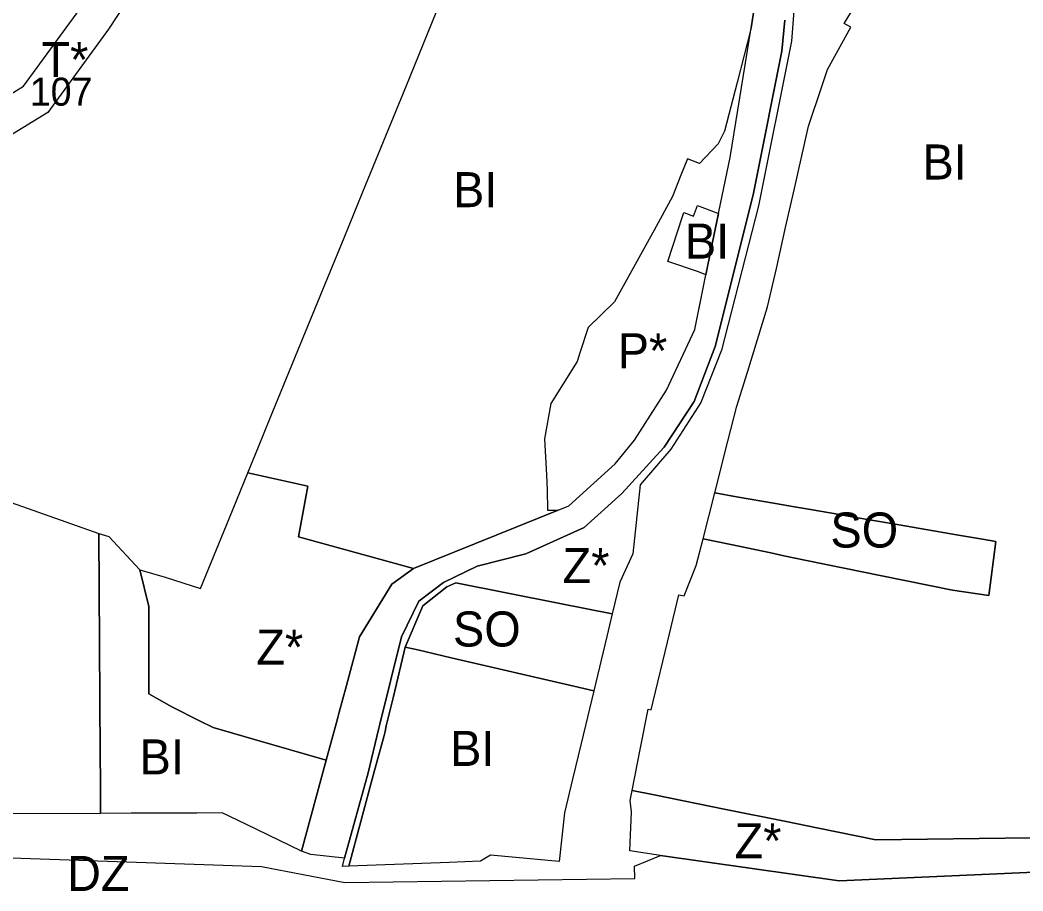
# Model space of a CAD drawing. Extents: x -521621 to -516769, y -1190068 to -1185078.
# Drawn here: x -519076.4 to -518790.4, y -1187170.7 to -1186922.3 of the extents above; entities that cross this region are included whole.
import ezdxf

# ---------------------------------------------------------------- set-up
doc = ezdxf.new("R2010")
doc.units = 0
for name, color, linetype in [('bydleni_s', 7, 'Continuous'), ('fpl_id', 7, 'Continuous'), ('s_zelen_s', 7, 'Continuous'), ('sm_vyuziti_s', 7, 'Continuous'), ('v_infrastr_n', 7, 'Continuous'), ('v_infrastr_s', 7, 'Continuous'), ('voda_s', 7, 'Continuous')]:
    doc.layers.add(name, color=color, linetype=linetype)

msp = doc.modelspace()

# ---------------------------------------------------------------- linework, layer by layer
at = {"layer": 'bydleni_s'}
for p, q in [((-518866.42, -1186914.8), (-518867.97, -1186924.47)), ((-518867.97, -1186924.47), (-518871.98, -1186940.13)), ((-518846.22, -1186936.39), (-518839.49, -1186924.32)), ((-518871.98, -1186940.13), (-518875.52, -1186953.98)), ((-518855.59, -1186970.29), (-518851.56, -1186952.52)), ((-518858.12, -1186981.47), (-518855.59, -1186970.29)), ((-518860.77, -1186993.13), (-518858.12, -1186981.47)), ((-518863.26, -1187004.11), (-518860.77, -1186993.13)), ((-518869.04, -1187022.77), (-518863.26, -1187004.11)), ((-519005.19, -1187036.06), (-518997.19, -1187016.52)), ((-518872.02, -1187032.4), (-518869.04, -1187022.77)), ((-518874.56, -1187042.38), (-518872.02, -1187032.4)), ((-519008.46, -1187044.05), (-519005.19, -1187036.06)), ((-518878.34, -1187057.18), (-518874.56, -1187042.38)), ((-518883.63, -1187077.91), (-518881.68, -1187070.28)), ((-518887.03, -1187086.48), (-518883.63, -1187077.91)), ((-518832.43, -1187156.14), (-518848.72, -1187152.83))]:
    msp.add_line(p, q, dxfattribs=at)
for points in [[(-518839.49, -1186924.32), (-518841.43, -1186923.31), (-518834.52, -1186911.88), (-518833.13, -1186912.44)], [(-518997.19, -1187016.52), (-518989.35, -1186997.36), (-518984.03, -1186984.36), (-518978.68, -1186971.28), (-518966.28, -1186940.98), (-518957.73, -1186920.08)], [(-518851.56, -1186952.52), (-518847.82, -1186941.21), (-518846.22, -1186936.39)], [(-518875.52, -1186953.98), (-518877.38, -1186957.58), (-518882.65, -1186963.16), (-518886.11, -1186961.88), (-518888.04, -1186966.5), (-518890.36, -1186972.63), (-518895.64, -1186982.24), (-518899.03, -1186988.43)], [(-518887.55, -1186978.34), (-518887.12, -1186977.18), (-518884.4, -1186978.2), (-518883.29, -1186975.22), (-518877.25, -1186977.48), (-518879.43, -1186987.93), (-518880.85, -1186994.95), (-518882.97, -1186994.14)], [(-518882.97, -1186994.14), (-518891.69, -1186991.15), (-518887.55, -1186978.34)], [(-518899.03, -1186988.43), (-518906.93, -1187002.63), (-518914.46, -1187009.96), (-518916.81, -1187017.23), (-518917.59, -1187019.65)], [(-518917.59, -1187019.65), (-518925.12, -1187031.63), (-518926.9, -1187041.73), (-518926.34, -1187052.15), (-518926.12, -1187056.17), (-518926.03, -1187062.09), (-518923.01, -1187062.07)], [(-518923.01, -1187062.07), (-518964.22, -1187078.77), (-518997.04, -1187069.74), (-518994.4, -1187055.27), (-519011.49, -1187051.47), (-519008.46, -1187044.05)], [(-518872.17, -1187058.25), (-518878.34, -1187057.18)], [(-518860.98, -1187060.18), (-518872.17, -1187058.25)], [(-518855.55, -1187061.12), (-518860.98, -1187060.18)], [(-518851.04, -1187061.9), (-518855.55, -1187061.12)], [(-518842.76, -1187063.33), (-518851.04, -1187061.9)], [(-518839.2, -1187063.95), (-518842.76, -1187063.33)], [(-518825.73, -1187066.28), (-518839.2, -1187063.95)], [(-518818.13, -1187067.59), (-518825.73, -1187066.28)], [(-518815.39, -1187068.07), (-518818.13, -1187067.59)], [(-518808.85, -1187069.2), (-518815.39, -1187068.07)], [(-519053.58, -1187131.78), (-519053.94, -1187068.75), (-519051.15, -1187069.57), (-519042.31, -1187079.1), (-519039.75, -1187089.57), (-519039.75, -1187094.22), (-519039.75, -1187105.62), (-519039.75, -1187114.45)], [(-518881.68, -1187070.28), (-518873.77, -1187071.92)], [(-518810.55, -1187084.93), (-518800.16, -1187086.44), (-518798.14, -1187071.02), (-518801.99, -1187070.37), (-518808.85, -1187069.2)], [(-518873.77, -1187071.92), (-518862.3, -1187074.3)], [(-518862.3, -1187074.3), (-518858.62, -1187075.07)], [(-518858.62, -1187075.07), (-518852.18, -1187076.4)], [(-518852.18, -1187076.4), (-518831.2, -1187080.76)], [(-518831.2, -1187080.76), (-518817.14, -1187083.6)], [(-518817.14, -1187083.6), (-518810.55, -1187084.93)], [(-518891.82, -1187099.7), (-518888.6, -1187086.21), (-518887.03, -1187086.48)], [(-518969.96, -1187115.24), (-518966.57, -1187101.13), (-518962.99, -1187101.96), (-518953.47, -1187104.19), (-518918.49, -1187112.34), (-518912.83, -1187113.66), (-518916.43, -1187128.63)], [(-518896.43, -1187119.01), (-518895.87, -1187116.65), (-518891.82, -1187099.7)], [(-519039.75, -1187114.45), (-519033.13, -1187118.17)], [(-518971.99, -1187123.65), (-518969.96, -1187115.24)], [(-519033.13, -1187118.17), (-519025.23, -1187122.16)], [(-518899.59, -1187130.34), (-518897.35, -1187118.82), (-518896.43, -1187119.01)], [(-519025.23, -1187122.16), (-519021.38, -1187124.1), (-519009.58, -1187127.51)], [(-518972.63, -1187126.32), (-518972.36, -1187125.21)], [(-518972.36, -1187125.21), (-518971.99, -1187123.65)], [(-519009.58, -1187127.51), (-518989.15, -1187133.41), (-518996.16, -1187159.32), (-519012.07, -1187151.66)], [(-518975.6, -1187137.35), (-518972.63, -1187126.32)], [(-518916.43, -1187128.63), (-518918.88, -1187138.79)], [(-518848.72, -1187152.83), (-518857.99, -1187150.94), (-518875.2, -1187147.44), (-518895.57, -1187143.29), (-518901.86, -1187142.01), (-518899.59, -1187130.34)], [(-519040.56, -1187148.55), (-519044.71, -1187148.56), (-519053.48, -1187148.58), (-519053.53, -1187139.7), (-519053.58, -1187131.78)], [(-518954.04, -1187162.56), (-518982.68, -1187163.67), (-518975.6, -1187137.35)], [(-518918.88, -1187138.79), (-518921.19, -1187148.39)], [(-519032.92, -1187148.54), (-519040.56, -1187148.55)], [(-519026.03, -1187148.52), (-519032.92, -1187148.54)], [(-519012.07, -1187151.66), (-519018.82, -1187148.41), (-519026.03, -1187148.52)], [(-518921.19, -1187148.39), (-518922.71, -1187162.32), (-518942.32, -1187160.52), (-518945.16, -1187162.22), (-518954.04, -1187162.56)], [(-518756.41, -1187158.62), (-518773.51, -1187155.4), (-518832.43, -1187156.14)]]:
    msp.add_lwpolyline(points, dxfattribs=at)
at = {"layer": 's_zelen_s'}
for p, q in [((-519016.75, -1187064.32), (-519011.49, -1187051.47)), ((-519024.99, -1187084.45), (-519016.75, -1187064.32)), ((-519042.31, -1187079.1), (-519035.1, -1187081.2)), ((-519035.1, -1187081.2), (-519024.99, -1187084.45)), ((-519039.75, -1187105.62), (-519039.75, -1187094.22)), ((-518979.61, -1187098.19), (-518983.39, -1187112.15))]:
    msp.add_line(p, q, dxfattribs=at)
for points in [[(-518855.26, -1186912.05), (-518856.49, -1186928.34)], [(-518859.24, -1186931.12), (-518858.39, -1186922.28)], [(-518856.49, -1186928.34), (-518865.87, -1186975.23)], [(-518866.74, -1186968.77), (-518859.24, -1186931.12)], [(-518867.42, -1186972.17), (-518866.74, -1186968.77)], [(-518878.19, -1187015.41), (-518867.42, -1186972.17)], [(-518865.87, -1186975.23), (-518876.39, -1187016.44)], [(-518884.19, -1187031.09), (-518878.19, -1187015.41)], [(-518876.39, -1187016.44), (-518882.26, -1187031.41)], [(-518892.72, -1187044.11), (-518884.19, -1187031.09)], [(-518882.26, -1187031.41), (-518890.88, -1187044.67)], [(-518890.88, -1187044.67), (-518899.59, -1187054.9)], [(-518894.94, -1187046.53), (-518892.72, -1187044.11)], [(-518904.86, -1187057.34), (-518894.94, -1187046.53)], [(-519011.49, -1187051.47), (-518994.4, -1187055.27), (-518997.04, -1187069.74)], [(-518899.59, -1187054.9), (-518901.68, -1187074.51), (-518905.37, -1187082.65)], [(-518915.56, -1187067.03), (-518904.86, -1187057.34)], [(-518932.2, -1187074.53), (-518915.56, -1187067.03)], [(-518997.04, -1187069.74), (-518964.22, -1187078.77), (-518970.38, -1187083.23), (-518979.61, -1187098.19)], [(-518946.05, -1187078.07), (-518932.2, -1187074.53)], [(-519039.75, -1187094.22), (-519039.75, -1187089.57), (-519042.31, -1187079.1)], [(-518955.73, -1187082.71), (-518946.05, -1187078.07)], [(-518962.68, -1187088.03), (-518955.73, -1187082.71)], [(-518954.73, -1187083.98), (-518961.55, -1187089.38)], [(-518952.19, -1187082.84), (-518954.73, -1187083.98)], [(-518922.5, -1187088.73), (-518952.19, -1187082.84)], [(-518905.37, -1187082.65), (-518907.55, -1187091.69), (-518922.5, -1187088.73)], [(-518967.66, -1187098.19), (-518962.68, -1187088.03)], [(-518961.55, -1187089.38), (-518966.57, -1187101.13)], [(-518973.8, -1187123.12), (-518967.66, -1187098.19)], [(-518966.57, -1187101.13), (-518969.96, -1187115.24)], [(-519021.38, -1187124.1), (-519025.23, -1187122.16), (-519033.13, -1187118.17), (-519039.75, -1187114.45), (-519039.75, -1187105.62)], [(-518983.39, -1187112.15), (-518985.44, -1187119.73), (-518985.85, -1187121.23), (-518986.23, -1187122.64)], [(-518969.96, -1187115.24), (-518971.99, -1187123.65)], [(-518986.23, -1187122.64), (-518989.15, -1187133.41), (-519009.58, -1187127.51), (-519021.38, -1187124.1)], [(-518977.21, -1187136.99), (-518974.18, -1187124.67)], [(-518974.18, -1187124.67), (-518973.8, -1187123.12)], [(-518972.36, -1187125.21), (-518972.63, -1187126.32)], [(-518971.99, -1187123.65), (-518972.36, -1187125.21)], [(-518972.63, -1187126.32), (-518975.6, -1187137.35)], [(-518983.9, -1187161.37), (-518977.21, -1187136.99)], [(-518975.6, -1187137.35), (-518982.68, -1187163.67)], [(-518902.05, -1187148.12), (-518902.42, -1187144.9), (-518901.86, -1187142.01), (-518895.57, -1187143.29), (-518875.2, -1187147.44)], [(-518787.19, -1187165.35), (-518842.9, -1187167.84), (-518893.85, -1187160.56), (-518902.51, -1187159.27), (-518902.05, -1187148.12)], [(-518875.2, -1187147.44), (-518857.99, -1187150.94), (-518848.72, -1187152.83), (-518832.43, -1187156.14)], [(-518832.43, -1187156.14), (-518773.51, -1187155.4), (-518756.41, -1187158.62), (-518757.5, -1187164.02), (-518787.19, -1187165.35)], [(-518984.47, -1187163.74), (-518983.9, -1187161.37)], [(-518982.68, -1187163.67), (-518984.47, -1187163.74)]]:
    msp.add_lwpolyline(points, dxfattribs=at)
at = {"layer": 'sm_vyuziti_s'}
for points in [[(-518825.73, -1187066.28), (-518818.13, -1187067.59), (-518815.39, -1187068.07), (-518808.85, -1187069.2), (-518801.99, -1187070.37), (-518798.14, -1187071.02), (-518800.16, -1187086.44), (-518810.55, -1187084.93), (-518817.14, -1187083.6), (-518831.2, -1187080.76), (-518852.18, -1187076.4), (-518858.62, -1187075.07), (-518862.3, -1187074.3), (-518873.77, -1187071.92), (-518881.68, -1187070.28), (-518878.34, -1187057.18), (-518872.17, -1187058.25), (-518860.98, -1187060.18), (-518855.55, -1187061.12), (-518851.04, -1187061.9), (-518842.76, -1187063.33)], [(-518842.76, -1187063.33), (-518839.2, -1187063.95), (-518825.73, -1187066.28)], [(-518966.57, -1187101.13), (-518961.55, -1187089.38), (-518954.73, -1187083.98), (-518952.19, -1187082.84), (-518922.5, -1187088.73), (-518907.55, -1187091.69), (-518909.09, -1187098.12), (-518912.83, -1187113.66)], [(-518912.83, -1187113.66), (-518918.49, -1187112.34), (-518953.47, -1187104.19), (-518962.99, -1187101.96), (-518966.57, -1187101.13)]]:
    msp.add_lwpolyline(points, dxfattribs=at)
at = {"layer": 'v_infrastr_n'}
msp.add_lwpolyline([(-519085.78, -1186947.47), (-519075.41, -1186941.15), (-519059.42, -1186919.2), (-519034.68, -1186881.46), (-519020.96, -1186857.56), (-519012.12, -1186862.24), (-519026.15, -1186886.69), (-519051.19, -1186924.89), (-519068.5, -1186948.65), (-519087.09, -1186959.97)], dxfattribs=at)
at = {"layer": 'v_infrastr_s'}
for points in [[(-518838.25, -1186879.01), (-518855.26, -1186912.05), (-518856.49, -1186928.34), (-518865.87, -1186975.23), (-518876.39, -1187016.44), (-518882.26, -1187031.41), (-518890.88, -1187044.67), (-518899.59, -1187054.9), (-518901.68, -1187074.51), (-518905.37, -1187082.65)], [(-518901.2, -1187163.65), (-518893.85, -1187160.56), (-518902.51, -1187159.27), (-518902.05, -1187148.12), (-518902.42, -1187144.9), (-518901.86, -1187142.01), (-518899.59, -1187130.34), (-518897.35, -1187118.82), (-518896.43, -1187119.01), (-518895.87, -1187116.65), (-518891.82, -1187099.7), (-518888.6, -1187086.21), (-518887.03, -1187086.48), (-518883.63, -1187077.91), (-518881.68, -1187070.28), (-518878.34, -1187057.18), (-518874.56, -1187042.38), (-518872.02, -1187032.4), (-518869.04, -1187022.77), (-518863.26, -1187004.11), (-518860.77, -1186993.13), (-518858.12, -1186981.47), (-518855.59, -1186970.29), (-518851.56, -1186952.52), (-518847.82, -1186941.21), (-518846.22, -1186936.39), (-518839.49, -1186924.32), (-518841.43, -1186923.31), (-518834.52, -1186911.88)], [(-518877.25, -1186977.48), (-518873.91, -1186961.51), (-518867.97, -1186924.47), (-518871.98, -1186940.13), (-518875.52, -1186953.98), (-518877.38, -1186957.58), (-518882.65, -1186963.16)], [(-518882.65, -1186963.16), (-518886.11, -1186961.88), (-518888.04, -1186966.5), (-518890.36, -1186972.63), (-518895.64, -1186982.24), (-518899.03, -1186988.43), (-518906.93, -1187002.63), (-518914.46, -1187009.96), (-518916.81, -1187017.23), (-518917.59, -1187019.65), (-518925.12, -1187031.63), (-518926.9, -1187041.73), (-518926.34, -1187052.15), (-518926.12, -1187056.17), (-518926.03, -1187062.09)], [(-518887.55, -1186978.34), (-518887.12, -1186977.18), (-518884.4, -1186978.2), (-518883.29, -1186975.22), (-518877.25, -1186977.48)], [(-518891.69, -1186991.15), (-518887.55, -1186978.34)], [(-518882.97, -1186994.14), (-518891.69, -1186991.15)], [(-518906.7, -1187048.84), (-518901.18, -1187042.16), (-518892.06, -1187027.83), (-518883.99, -1187010.53), (-518880.85, -1186994.95)], [(-518880.85, -1186994.95), (-518882.97, -1186994.14)], [(-518926.03, -1187062.09), (-518923.01, -1187062.07), (-518919.97, -1187060.84), (-518906.7, -1187048.84)], [(-518905.37, -1187082.65), (-518907.55, -1187091.69)], [(-518907.55, -1187091.69), (-518909.09, -1187098.12), (-518912.83, -1187113.66), (-518916.43, -1187128.63), (-518918.88, -1187138.79), (-518921.19, -1187148.39), (-518922.71, -1187162.32)], [(-518922.71, -1187162.32), (-518942.32, -1187160.52), (-518945.16, -1187162.22), (-518954.04, -1187162.56), (-518982.68, -1187163.67), (-518984.47, -1187163.74), (-518983.9, -1187161.37), (-518993.51, -1187160.27), (-518996.16, -1187159.32), (-519012.07, -1187151.66), (-519018.82, -1187148.41), (-519026.03, -1187148.52), (-519032.92, -1187148.54), (-519040.56, -1187148.55), (-519044.71, -1187148.56), (-519053.48, -1187148.58), (-519095.75, -1187148.68), (-519103.69, -1187148.5), (-519107.05, -1187148.43), (-519108.66, -1187148.39)], [(-519109.24, -1187160.25), (-519007.58, -1187163.74), (-518983.81, -1187168.29), (-518901.11, -1187167.15), (-518901.2, -1187163.65)], [(-519109.24, -1187160.25), (-519007.58, -1187163.74)], [(-518901.2, -1187163.65), (-518893.85, -1187160.56)], [(-518893.85, -1187160.56), (-518842.9, -1187167.84)], [(-519007.58, -1187163.74), (-518983.81, -1187168.29)], [(-518901.11, -1187167.15), (-518901.2, -1187163.65)], [(-518842.9, -1187167.84), (-518787.19, -1187165.35)], [(-518983.81, -1187168.29), (-518901.11, -1187167.15)]]:
    msp.add_lwpolyline(points, dxfattribs=at)
msp.add_lwpolyline([(-519095.75, -1187148.68), (-519095.71, -1187138.47), (-519095.7, -1187134.66), (-519095.67, -1187125.65), (-519095.65, -1187120.65), (-519095.47, -1187069.4), (-519095.24, -1187058.86), (-519085.06, -1187059.33), (-519080.57, -1187059.34), (-519053.94, -1187068.75), (-519053.58, -1187131.78), (-519053.53, -1187139.7), (-519053.48, -1187148.58)], close=True, dxfattribs=at)
at = {"layer": 'voda_s'}
for points in [[(-518993.51, -1187160.27), (-518996.16, -1187159.32), (-518989.15, -1187133.41), (-518986.23, -1187122.64), (-518985.85, -1187121.23), (-518985.44, -1187119.73), (-518983.39, -1187112.15), (-518979.61, -1187098.19), (-518970.38, -1187083.23), (-518964.22, -1187078.77), (-518923.01, -1187062.07), (-518919.97, -1187060.84), (-518906.7, -1187048.84), (-518901.18, -1187042.16), (-518892.06, -1187027.83), (-518883.99, -1187010.53), (-518879.43, -1186987.93), (-518873.91, -1186961.51), (-518867.97, -1186924.47), (-518866.42, -1186914.8)], [(-518858.39, -1186922.28), (-518859.24, -1186931.12)], [(-518859.24, -1186931.12), (-518866.74, -1186968.77)], [(-518866.74, -1186968.77), (-518867.42, -1186972.17)], [(-518867.42, -1186972.17), (-518878.19, -1187015.41)], [(-518878.19, -1187015.41), (-518884.19, -1187031.09)], [(-518884.19, -1187031.09), (-518892.72, -1187044.11)], [(-518892.72, -1187044.11), (-518894.94, -1187046.53)], [(-518894.94, -1187046.53), (-518904.86, -1187057.34)], [(-518904.86, -1187057.34), (-518915.56, -1187067.03)], [(-518915.56, -1187067.03), (-518932.2, -1187074.53)], [(-518932.2, -1187074.53), (-518946.05, -1187078.07)], [(-518946.05, -1187078.07), (-518955.73, -1187082.71)], [(-518955.73, -1187082.71), (-518962.68, -1187088.03)], [(-518962.68, -1187088.03), (-518967.66, -1187098.19)], [(-518967.66, -1187098.19), (-518973.8, -1187123.12)], [(-518974.18, -1187124.67), (-518977.21, -1187136.99)], [(-518973.8, -1187123.12), (-518974.18, -1187124.67)], [(-518977.21, -1187136.99), (-518983.9, -1187161.37)], [(-518983.9, -1187161.37), (-518993.51, -1187160.27)]]:
    msp.add_lwpolyline(points, dxfattribs=at)

# ---------------------------------------------------------------- texts
at = {"layer": 'bydleni_s'}
for p in [(-518819.09, -1186967.77), (-518952.96, -1186975.66), (-518886.85, -1186990.33), (-518953.79, -1187135.05), (-519042.35, -1187137.47)]:
    msp.add_text('BI', height=10, dxfattribs=at).set_placement(p)
at = {"layer": 'fpl_id'}
msp.add_text('107', height=8, dxfattribs=at).set_placement((-519073.65, -1186946.71))
at = {"layer": 's_zelen_s'}
for p in [(-518921.72, -1187082.88), (-519009.06, -1187106.15), (-518872.68, -1187161.39)]:
    msp.add_text('Z*', height=10, dxfattribs=at).set_placement(p)
at = {"layer": 'sm_vyuziti_s'}
for p in [(-518845.35, -1187072.75), (-518952.98, -1187100.98)]:
    msp.add_text('SO', height=10, dxfattribs=at).set_placement(p)
at = {"layer": 'v_infrastr_n'}
msp.add_text('T*', height=10, dxfattribs=at).set_placement((-519070.33, -1186938.57))
at = {"layer": 'v_infrastr_s'}
for s, p in [('P*', (-518906, -1187021.62)), ('DZ', (-519063.04, -1187170.71))]:
    msp.add_text(s, height=10, dxfattribs=at).set_placement(p)

doc.saveas('drawing.dxf')
